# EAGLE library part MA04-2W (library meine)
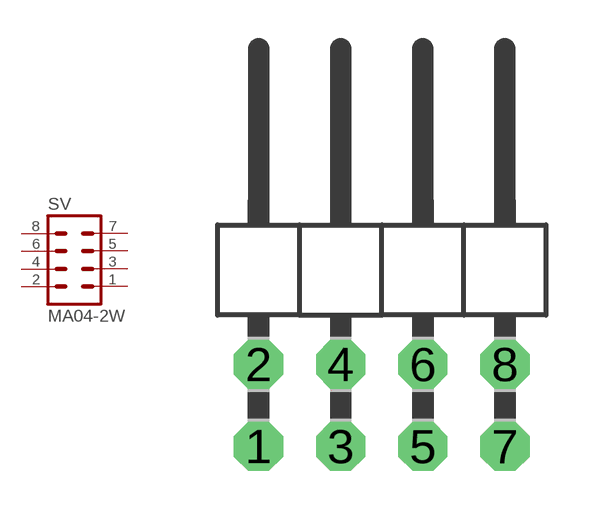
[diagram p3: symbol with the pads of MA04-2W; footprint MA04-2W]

Designator prefix SV

## MA04-2W  [MA04-2W]
1  1  pas
2  2  pas
3  3  pas
4  4  pas
5  5  pas
6  6  pas
7  7  pas
8  8  pas

## Footprint MA04-2W (pad centres in mm)
drill 1.016 octagon: 1 -3.81,-1.27; 2 -3.81,1.27; 3 -1.27,-1.27; 4 -1.27,1.27; 5 1.27,-1.27; 6 1.27,1.27; 7 3.81,-1.27; 8 3.81,1.27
